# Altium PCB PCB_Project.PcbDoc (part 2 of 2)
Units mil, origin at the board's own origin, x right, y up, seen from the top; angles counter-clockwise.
Board outline 8500 x 3000 mil, 2 copper layers (Top Layer, Bottom Layer), stack 62 mil thick; 123 components, 59 nets, 356 pads, 0 vias.
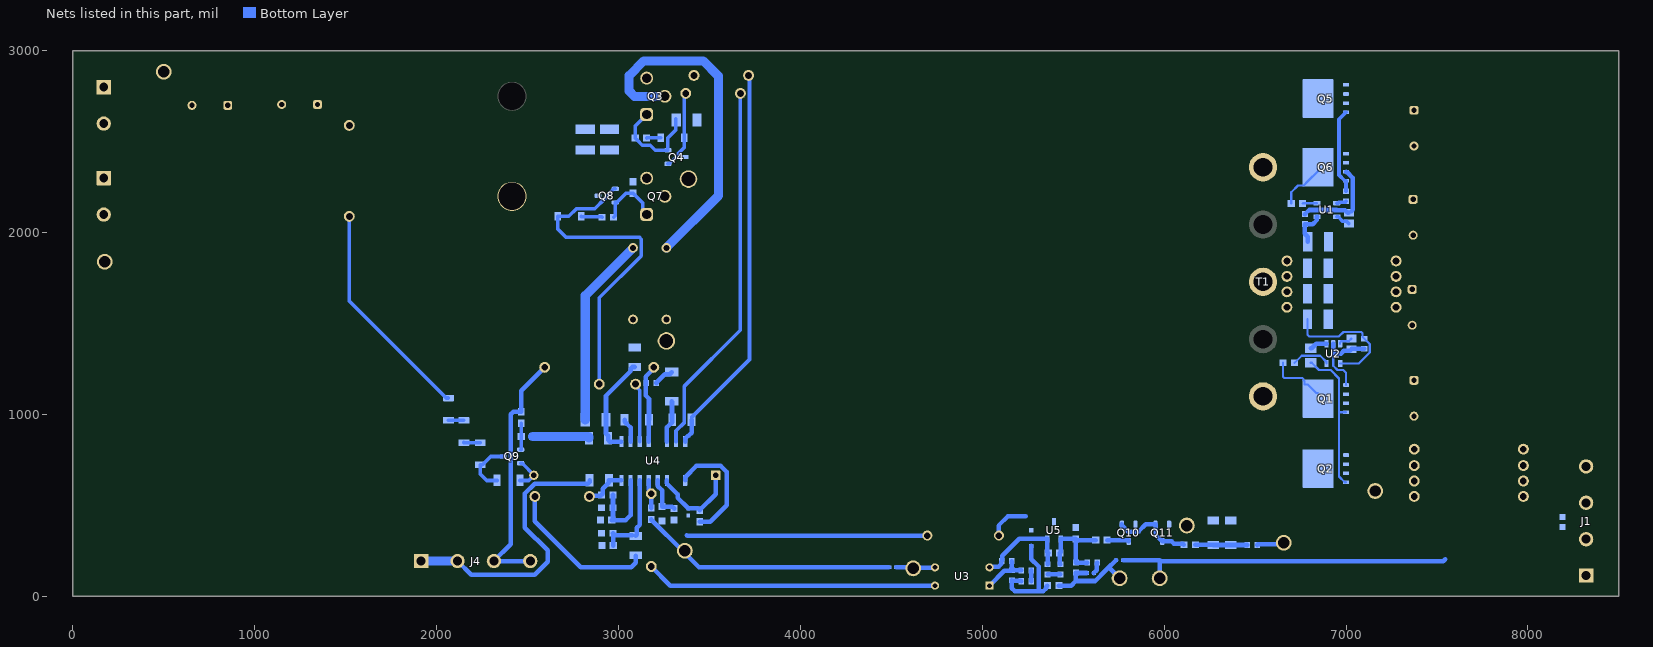
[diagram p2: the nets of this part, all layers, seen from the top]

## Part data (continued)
R16: library part CMP-0022684-3, "RES, 10.0 k, 1%, 0.1 W, 0603", Manufacturer=Panasonic, Power_W=100mW, Supplier Part Number 1=P10.0KHCT-ND, TempCo="100 ppm/C", Tolerance_%=1%, Value2=0.1W, Value_Code=10k0, ValueDisplayed=10.0k
R17 R19 R25: library part CMP-0087456-2, "3.3 MOhms ±1% 0.25W, 1/4W Chip Resistor 1206 (3216 Metric) Automotive AEC-Q200, High Voltage Thick Film", Manufacturer="Rohm Semiconductor", Power_W=250mW, TempCo=100ppm/°C, Tolerance_%=1%
R18: library part CMP-0026658-1, "RES, 10.0 k, 1%, 0.1 W, 0402", Manufacturer=Panasonic, Power_W=100mW, Supplier Part Number 1=P10.0KLCT-ND, TempCo="100 ppm/C", Tolerance_%=1%, Value2=0.1W, Value_Code=10k0, ValueDisplayed=10.0k
R20 R22: library part CMP-0023036-5, "RES, 33.2 k, 1%, 0.1 W, 0603", Manufacturer=Yageo, Power_W=100mW, Supplier Part Number 1=311-33.2KHRCT-ND, TempCo="100 ppm/C", Tolerance_%=1%, Value2=0.1W, Value_Code=33k2, ValueDisplayed=33.2k
R21: library part CMP-0022109-5, "RES, 1.00 k, 1%, 0.1 W, AEC-Q200 Grade 0, 0603", Manufacturer=Vishay-Dale, Power_W=100mW, Supplier Part Number 1=541-1.00KHCT-ND, TempCo="100 ppm/C", Tolerance_%=1%, Value2=0.1W, Value_Code=1k00, ValueDisplayed=1.00k
R23: library part CMP-0022735-5, "RES, 100 k, 1%, 0.1 W, 0603", Manufacturer=Yageo, Power_W=100mW, Supplier Part Number 1=311-100KHRCT-ND, TempCo="100 ppm/C", Tolerance_%=1%, Value2=0.1W, Value_Code=100k
R24: library part CMP-0016956-3, "RES, 3.01 M, 1%, 0.25 W, AEC-Q200 Grade 0, 1206", Manufacturer=Vishay-Dale, Power_W=250mW, Supplier Part Number 1=541-3.01MFCT-ND, TempCo="100 ppm/C", Tolerance_%=1%, Value2=0.25W, Value_Code=3M01, ValueDisplayed=3.01M
R26: library part CMP-0021990-4, "RES, 100 k, 1%, 0.1 W, AEC-Q200 Grade 0, 0603", Manufacturer=Vishay-Dale, Power_W=100mW, Supplier Part Number 1=541-100KHCT-ND, TempCo="100 ppm/C", Tolerance_%=1%, Value2=0.1W, Value_Code=100k
R27: library part CMP-0093609-1, "0Ω ±0 0.25W 1206 Thick Film Chip Resistor AEC-Q200 compliant", Manufacturer="Stackpole Electronics", Operating Temperature Range="-55°C to +155°C", Power_W=250mW
R28: library part CMP-0022763-5, "RES, 11.0 k, 1%, 0.1 W, 0603", Manufacturer=Yageo, Power_W=100mW, Supplier Part Number 1=311-11.0KHRCT-ND, TempCo="100 ppm/C", Tolerance_%=1%, Value2=0.1W, Value_Code=11k0, ValueDisplayed=11.0k
R30: library part CMP-0096703-1, "NTC Thermistor 470k 0603 (1608 Metric)", B Tolerance=3%, Digikey Part Number=495-B57371V2474J060CT-ND, Manufacturer=TDK, Mouser Part Number=871-B57371V2474J060, Operating Temperature Range="-55°C to +125°C", Power_W=180mW, Tolerance_%=5%
R31: library part CMP-0022828-5, "RES, 16.2 k, 1%, 0.1 W, 0603", Manufacturer=Yageo, Power_W=100mW, Supplier Part Number 1=311-16.2KHRCT-ND, TempCo="100 ppm/C", Tolerance_%=1%, Value2=0.1W, Value_Code=16k2, ValueDisplayed=16.2k
R32: library part CMP-0022941-4, "RES, 249 k, 1%, 0.1 W, 0603", Manufacturer=Yageo, Power_W=100mW, Supplier Part Number 1=311-249KHRCT-ND, TempCo="100 ppm/C", Tolerance_%=1%, Value2=0.1W, Value_Code=249k
R33: library part CMP-0023050-5, "RES, 35.7 k, 1%, 0.1 W, 0603", Manufacturer=Yageo, Power_W=100mW, Supplier Part Number 1=311-35.7KHRCT-ND, TempCo="100 ppm/C", Tolerance_%=1%, Value2=0.1W, Value_Code=35k7, ValueDisplayed=35.7k
R34: library part CMP-0023343-3, "RES, 0, 1%, 0.1 W, AEC-Q200 Grade 0, 0603", Manufacturer="Stackpole Electronics Inc", Power_W=100mW, Supplier Part Number 1=RMCF0603ZT0R00CT-ND, TempCo=ppm/C, Tolerance_%=1%, Value2=0.1W, Value_Code=0
T1: library part CMP-0120310-1, "Backlight LLC Transformer", Frequency_Fixed=80-250kHz, Manufacturer="Payton Planar", Operating Temperature Range=to, Voltage_Isolation_Vrms=2500VDC
TP5 Vin: library part CMP-0055147-2, "Test Point, Multipurpose, Red, TH", Color=Red, Manufacturer="Keystone Electronics", Supplier Part Number 1=36-5010-ND
TP6: library part CMP-0055150-2, "Test Point, Multipurpose, Orange, TH", Color=Orange, Manufacturer="Keystone Electronics", Supplier Part Number 1=36-5013-ND
TP7 TP8: library part CMP-0055149-2, "Test Point, Multipurpose, White, TH", Color=White, Manufacturer="Keystone Electronics", Supplier Part Number 1=36-5012-ND
U1 U2: library part CMP-0013047-3, "High-Frequency Multi-Mode Synchronous Rectifier Controller, DBV0005A (SOT-23-5)", Alternate Manufacturer="Texas Instruments", Alternate PartNumber=UCC24612-2DBVR
U3: library part CMP-0083653-1, "Optocoupler, 5.3 kV, 100-200% CTR, SMT", Manufacturer=Vishay-Semiconductor, Supplier Part Number 1=VO618A-3-ND, Voltage_Isolation_Vrms=5.3kV
U4: library part CMP-0095299-1, "750kHz Wide VIN/VOUT Range LLC Controller Optimized for Light Load Efficiency", Manufacturer="Texas Instruments", Max Supply Voltage=18.5V, Operating Temperature Range="-40°C to +150°C", Switching Frequency=30-750kHz
U5: library part CMP-0033066-1, "Low-Voltage Adjustable Precision Shunt Regulator, 129 ppm / degC, 80 mA, 0 to 70 degC, 3-pin SOT-23 (DBZ), Green (RoHS & no Sb/Br)", Manufacturer="Texas Instruments", Rating=Catalog, Temp Coeff(Max)(ppm/ degree C)=129

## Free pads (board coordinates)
  round 160 hole 150: 2(2414.9,2200) 2(2414.9,2750)

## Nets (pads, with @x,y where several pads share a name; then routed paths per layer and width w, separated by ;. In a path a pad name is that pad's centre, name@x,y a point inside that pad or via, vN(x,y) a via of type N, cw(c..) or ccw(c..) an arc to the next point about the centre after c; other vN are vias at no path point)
5VP_BL: C20.1 J14.2 R26.2 U4.8 | length 236.9
  Bottom Layer w25: J14.2@2840,550 2844.21,554.21 2902.49,554.21 R26.2@2906.7,558.42 2907.68,558.42 2913.88,564.62 2913.88,592.7 2947.09,625.91 C20.1@2947.09,638.7 U4.8@3016.26,638.7
BLK_BL: C32.1 J15.1 R33.2 U4.3 | length 498.9
  Bottom Layer w25: U4.3@3266.26,638.7 3266.26,621.38 3324.75,562.88 3324.75,542.49 C32.1@3382.56,484.68 3436.51,484.68 3439.8,481.39 3440.79,481.39 R33.2@3446.99,475.19 ; R33.2@3446.99,474.21 R33.2@3446.99,475.19 ; J15.1@3534.61,666.26 3534.61,562.81 R33.2@3446.99,475.19
EVDD: C2.2 C3.2 C8.2 C9.2 C12.1 J1.1 J1.2 J5.2 J6.2 J7.2 J8.2 R10.2 TP5.1 | length 1868.8
  Bottom Layer w25: R10.2@5774.69,200 5975,200 ; TP5.1@5975,100 5975,193.87 7533.87,193.87 7545,205
FB_BL: C24.1 J13.1 U4.5 | length 157.9
  Bottom Layer w25: U4.5@3166.26,638.7 3166.95,638.01 3166.95,587.52 3180,574.47 J13.1@3180,565 C24.1@3180,486.5
HO_BL: J18.1 U4.15 | length 2061.5
  Bottom Layer w20: U4.15@3316.26,851.3 3316.26,910.8 3362.36,956.9 3362.36,1156.88 3670,1464.51 J18.1@3670,2766.25
HS_BL: C26.2 J17.1 U4.16 | length 2133
  Bottom Layer w20: C26.2@3401.89,971.51 3401.89,984.31 3720,1302.42 3720,2835
  Bottom Layer w25: U4.16@3366.26,851.3 3366.26,868.62 3382.56,884.92 3387.25,884.92 3401.89,899.56 C26.2@3401.89,971.51
HVBUS: C1.1 C6.2 C7.2 C36.1 C37.1 J2.1 J2.2 J19.2 Q3.2 Vin.1 | length 1910.3
  Bottom Layer w50: Q3.2@3249.43,2750 3087.63,2750 3058.34,2779.29 3058.34,2863.34 3140,2945 3465.71,2945 3550,2860.71 3550,2203.54 C1.1@3263.31,1916.85
ISNS_BL: C13.2 C16.1 R5.2 U4.9 | length 555.8
  Bottom Layer w25: U4.9@3016.26,851.3 2952.3,851.3 2943.15,860.45 C16.1@2943.15,870.49 2943.15,883.28 2931.34,895.1 R5.2@2931.34,971.51 2931.34,1104.59 3066.65,1239.9 3066.65,1252.7 3075.81,1261.85 C13.2@3088.6,1261.85
LLC_VCC_BL: J4.3 J4.4 J20.2 R29.2 | length 1405.8
  Bottom Layer w25: J4.4@2515,195 J4.3@2315,195 2407.82,287.82 2407.82,1001.16 2422.46,1015.8 R29.2@2465.51,1015.8 2465.51,1131.39 J20.2@2594.12,1260
LO_BL: J16.1 U4.11 | length 325.2
  Bottom Layer w20: J16.1@3094.12,1167.36 3094.12,1156.54 3116.26,1134.4 U4.11@3116.26,851.3
NetC1_2: C1.2 C13.1 C14.1 Cr.1
NetC12_2: C12.2 J1.3 J1.4 J9.2 J10.2 J11.2 J12.2
NetC18_1: C18.1 U1.3 | length 81.2
  Bottom Layer w20: U1.3@6949.13,2087.6 6957.01,2087.6 6982.48,2062.13 7003.35,2062.13 C18.1@7015,2050.47
NetC19_1: C19.1 D4.1 R11.2 R34.1 | length 583.3
  Bottom Layer w25: C19.1@5214.88,83.66 5211.91,86.63 5165.41,86.63 R11.2@5162.44,89.6 5162.44,45.53 5177.97,30 5310,30 ; D4.1@5270,277.73 5270,204.95 5310,164.95 5310,30 ; R34.1@5358.26,60 5357.28,60 5351.08,53.8 5351.08,44.64 5336.43,30 5310,30
NetC19_2: C19.2 R8.2 | length 60
  Bottom Layer w25: C19.2@5270,83.66 R8.2@5270,143.66
NetC22_1: C22.1 U2.3 | length 79.7
  Bottom Layer w12: U2.3@6967.4,1389.13 6967.4,1397.01 6973.4,1403.01 7014.56,1403.01 C22.1@7030.22,1418.66
NetC23_1: C23.1 R10.1 R14.2 R34.2 TP6.1 | length 563.1
  Bottom Layer w25: R34.2@5421.26,60 5489.14,60 5514.25,85.11 ; R14.2@5514.25,131.47 5514.25,85.11 ; R14.2@5517.68,129.03 C23.1@5574.56,129.03 ; R10.1@5735.31,200 5689.8,154.48 ; TP6.1@5755,100 5700.52,154.48 5689.8,154.48 ; 5514.25,85.11 5620.48,85.11 5679.86,144.49 5679.86,144.54 5689.8,154.48
NetC23_2: C23.2 R16.2 | length 65
  Bottom Layer w25: C23.2@5613.94,129.03 5628.56,143.66 5628.56,183.34 R16.2@5631.81,186.59
NetC25_1: C25.1 R14.1 R16.1 R20.1 R22.2 R28.2 U5.1 | length 531.3
  Bottom Layer w25: R20.1@5429.25,176.59 5428.99,176.59 5425.75,179.84 C25.1@5425.75,239.03 5430.96,244.25 5430.96,316.1 U5.1@5431.65,316.79 R28.2@5514.25,316.79 R28.2@5514.25,316.2 ; R16.1@5576.69,186.59 R14.1@5514.25,186.59 R28.2@5514.25,316.2 ; R22.2@5623.5,310 5520.45,310 R28.2@5514.25,316.2
NetC25_2: C25.2 C27.2 R13.1 U3.2 U5.2 | length 548.8
  Bottom Layer w25: U3.2@5040,160 5043.88,163.88 5089.55,163.88 5104.19,178.52 5104.19,191.75 5110.69,198.25 5110.69,224.11 5203.37,316.79 U5.2@5356.85,316.79 5357.54,316.1 5357.54,244.25 C25.2@5362.75,239.03 5361,237.28 5361,178.34 C27.2@5359.25,176.59
NetC26_1: C26.1 D3.1 U4.14 | length 235.2
  Bottom Layer w25: U4.14@3266.26,851.3 3266.26,929.39 3295.59,958.72 C26.1@3295.59,971.51 3294.21,972.89 3294.21,1071.81 D3.1@3292.83,1073.18
NetC27_1: C27.1 R20.2 | length 70
  Bottom Layer w25: C27.1@5359.25,121.47 R20.2@5429.25,121.47
NetC28_1: C28.1 C29.1 R21.1 R23.2 | length 286.7
  Bottom Layer w25: R23.2@6171.5,285 6172.46,284.04 6269.04,284.04 C29.1@6270,283.07 C28.1@6365,283.07 R21.1@6457.44,283.07
NetC30_1: C30.1 R30.2 U4.4 | length 225.1
  Bottom Layer w25: U4.4@3216.26,638.7 3216.26,606.44 3239.68,583.01 R30.2@3239.68,494.15 3295.66,494.15 3305.5,484.31 C30.1@3305.5,483.32
NetC31_1: C31.1 R24.1 R32.2 U4.6 | length 491.7
  Bottom Layer w25: R32.2@2969.69,347.43 2970.67,347.43 2981.02,337.09 3065,337.09 R24.1@3075.83,337.09 ; R32.2@2970.59,346.53 2970.59,337.09 2970.59,280.9 C31.1@2971.5,280 ; R24.1@3095,333.15 3100.72,338.87 3100.72,377.66 3116.26,393.19 U4.6@3116.26,638.7
NetC33_1: C33.1 Q9.1 R29.1 | length 147.6
  Bottom Layer w20: Q9.1@2462.24,807.4 2463.7,807.4 2465.51,809.21 C33.1@2465.51,879.8 R29.1@2465.51,952.81
NetC34_1: C34.1 R26.1 R31.2 U4.7 | length 446.6
  Bottom Layer w25: C34.1@2963.31,420.33 C34.1@2963.49,420.33 ; R26.1@2969.69,558.42 R31.2@2969.69,488.26 2969.69,426.53 C34.1@2963.49,420.33 ; U4.7@3066.26,638.7 3066.26,446.57 3040.02,420.33 C34.1@2963.49,420.33
NetC35_1: C35.1 J20.1 R15.1 U4.12 | length 435.3
  Bottom Layer w25: U4.12@3166.26,851.3 3166.95,851.99 3166.95,970.78 C35.1@3167.68,971.51 3167.68,1086.93 3149.48,1105.13 3149.48,1174.25 3149.48,1209.18 3194.12,1253.82 J20.1@3194.12,1260
NetD1_1: D1.1 R1.1 | length 79.1
  Bottom Layer w20: R1.1@3154.76,2520.74 3155.78,2521.76 3232.01,2521.76 D1.1@3233.03,2522.77
NetD1_2: D1.2 J18.2 Q4.1 | length 401.5
  Bottom Layer w20: Q4.1@3271.78,2378.71 3279.65,2378.71 3328.71,2427.76 3328.71,2435.64 3361.97,2468.89 D1.2@3361.97,2522.77 J18.2@3361.97,2738.28
NetD2_1: D2.1 R3.1 | length 117.6
  Bottom Layer w20: D2.1@2794.47,2090 2796.97,2087.5 2907.5,2087.5 R3.1@2910,2085
NetD2_2: D2.2 J16.2 Q8.1 | length 1826.2
  Bottom Layer w20: J16.2@2894.12,1167.36 2894.12,1642.15 3124.45,1872.48 3124.45,1964.19 3112.73,1975.91 2709.63,1975.91 2665.53,2020 D2.2@2665.53,2090 2727.16,2090 2769.05,2131.89 2869.4,2131.89 2925.51,2188 2925.51,2192.1 2974.56,2241.16 Q8.1@2982.44,2241.16
NetD3_2: D3.2 R15.2 | length 112.5
  Bottom Layer w25: R15.2@3208.94,1172.88 R15.2@3207.56,1174.25 3207.56,1175.24 3254.23,1221.91 3280.93,1221.91 D3.2@3292.83,1233.82
NetHS_1: HS.1 J17.2 Q3.3 Q4.3 Q7.2 R2.1
NetJ13_2: J13.2 U3.4 | length 1603.5
  Bottom Layer w25: J13.2@3180,165 3285,60 U3.4@4740,60
NetJ14_1: J14.1 R24.2 | length 844.5
  Bottom Layer w25: J14.1@2540,550 2540,413.41 2793.41,160 3069.49,160 3095,185.51 R24.2@3095,222.91
NetJ15_2: J15.2 Q9.2 R27.1 | length 189.2
  Bottom Layer w20: R27.1@2457.99,638.01 2506.36,638.01 J15.2@2534.61,666.26 2534.61,668.11 2470.12,732.6 Q9.2@2462.24,732.6
NetJ19_1: J19.1 R17.2 | length 1231.6
  Bottom Layer w20: J19.1@1520,2090 1520,1624.21 2053.19,1091.02 R17.2@2065,1091.02
NetQ3_1: Q3.1 Q4.2 R1.2 R2.2 | length 538.7
  Bottom Layer w20: R1.2@3091.77,2520.74 3091.77,2586.77 Q3.1@3155,2650 ; R1.2@3101.45,2510.38 3131.34,2480.49 3174.47,2480.49 3201.45,2453.51 Q4.2@3271.78,2453.51 3271.78,2521.47 3315,2564.69 R2.2@3315,2624.93
NetQ7_1: Q7.1 Q8.2 R3.2 R4.2 | length 352.8
  Bottom Layer w20: R3.2@2972.99,2085 2973.74,2085 2982.44,2093.7 Q8.2@2982.44,2166.35 2990.31,2166.35 3041.33,2217.37 R4.2@3080,2217.37 3080,2216.39 3134.33,2162.05 3134.33,2120.67 Q7.1@3155,2100
NetQ9_3: Q9.3 R25.1 R27.2 | length 304.3
  Bottom Layer w20: R27.2@2332.01,638.01 2275,638.01 2240,673.01 R25.1@2240,723.98 2251.81,723.98 2297.83,770 Q9.3@2367.76,770
NetQ10_1: Q10.1 Q11.1 Q11.3 R23.1 | length 461.6
  Bottom Layer w25: Q10.1@5767.6,397.24 5767.6,390.75 5801.16,357.18 5859.19,357.18 5899.25,397.24 Q11.1@5952.6,397.24 5952.6,340.16 5982.81,309.94 5989.31,309.94 5990,309.25 Q11.3@5990,302.76 6040.69,302.76 6052.24,291.2 6102.3,291.2 R23.1@6108.5,285
NetQ10_3: Q10.3 R22.1 | length 125.3
  Bottom Layer w25: R22.1@5686.5,310 5804.25,310 5805,309.25 Q10.3@5805,302.76
NetR6_1: R6.1 U1.5 | length 80.4
  Bottom Layer w12: R6.1@6761.5,2160 6763.9,2162.4 U1.5@6840.87,2162.4
NetR7_2: R7.2 U1.1 | length 55
  Bottom Layer w20: U1.1@6949.13,2162.4 6957.01,2162.4 6961.3,2166.69 6994.21,2166.69 R7.2@6999.96,2172.44
NetR8_1: R8.1 R11.1 R13.2 U3.1 | length 260.7
  Bottom Layer w25: U3.1@5040,60 5121.47,141.47 5159.19,141.47 R11.1@5162.44,144.72 ; R13.2@5162.56,195 5162.5,194.94 5162.5,144.78 R11.1@5162.44,144.72 ; R8.1@5214.88,143.66 5214.35,144.19 5162.97,144.19 R11.1@5162.44,144.72
NetR9_1: R9.1 U2.5 | length 214.6
  Bottom Layer w12: R9.1@6716.5,1285 6717.48,1285 6756.35,1323.87 6857.46,1323.87 6892.6,1288.74 U2.5@6892.6,1280.87
NetR12_1: R12.1 U2.1 | length 97.6
  Bottom Layer w25: R12.1@6805,1365 6811.5,1365 6835.63,1389.13 U2.1@6892.6,1389.13
NetR17_1: R17.1 R19.2 | length 85.3
  Bottom Layer w20: R17.1@2065,968.98 2065.34,968.64 2149.66,968.64 R19.2@2150,968.3
NetR18_2: R18.2 TP7.1 U3.3 | length 217.3
  Bottom Layer w25: R18.2@4527.26,160 4614.48,160 TP7.1@4620,154.48 4622.76,157.24 4737.24,157.24 U3.3@4740,160
NetR19_1: R19.1 R25.2 | length 90.1
  Bottom Layer w20: R19.1@2150,846.26 2150.12,846.14 2239.88,846.14 R25.2@2240,846.02
NetR21_2: R21.2 TP8.1 | length 150.5
  Bottom Layer w25: R21.2@6512.56,283.07 6512.56,284.06 6515.81,287.3 6649.8,287.3 TP8.1@6657.5,295
PGND: C6.1 C7.1 C14.2 C15.2 C16.2 C20.2 C24.2 C30.2 C31.2 C32.2 C33.2 C34.2 C35.2 C36.2 C37.2 J3.1 J3.2 J4.1 J4.2 pad.2@2414.9,2200 PGND.1 Q7.3 Q8.3 R4.1 R5.1 R18.1 R30.1 R31.1 R32.1 R33.1 TP4.1 U4.1 U4.10 | length 6470.3
  Bottom Layer w25: J4.2@2115,195 2190,120 2539.3,120 2610.08,190.78 2610.08,253.58 2485,378.66 2485,566.24 2539.06,620.3 2831.63,620.3 2840.79,629.45 C20.2@2840.79,638.7 ; C35.2@3033.82,971.51 3033.82,961.67 3066.26,929.23 U4.10@3066.26,851.3 ; C24.2@3180,423.5 3180,422.52 3358.03,244.49 3442.52,160 R18.1@4485.93,160 ; U4.1@3366.26,638.7 3366.26,656.02 3427.84,717.6 3562.06,717.6 3594.87,684.79 3594.87,502.25 3503.84,411.22 R33.1@3446.99,411.22 ; 3375,337.09 3377.09,335 C15.2@4698.15,335
  Bottom Layer w50: J4.1@1915,195 J4.2@2115,195 ; C33.2@2528.5,879.8 2833.5,879.8 2836.85,876.46 C16.2@2836.85,870.49 ; R5.1@2817.17,971.51 2817.17,1654.02 C14.2@3080,1916.85
SGND: C2.1 C3.1 C4.1 C5.1 C8.1 C9.1 C10.2 C11.2 C15.1 C17.2 C18.2 C21.2 C22.2 C28.2 C29.2 D4.2 J9.1 J10.1 J11.1 J12.1 Q1.1 Q1.2 Q1.3 Q2.1 Q2.2 Q2.3 Q5.1 Q5.2 Q5.3 Q6.1 Q6.2 Q6.3 Q10.2 Q11.2 R28.1 TP1.1 TP2.1 U1.2 U2.2 U5.3 | length 1176.6
  Bottom Layer w12: 6930,1335 6930,1268.33 6953.19,1245.14 6984.82,1245.14 6999.96,1230 Q1.1@6999.96,1162.64
  Bottom Layer w25: C15.1@5091.85,335 5089.55,337.3 5089.55,389.97 5139.58,440 5240,440 ; C17.2@6773.37,2102.56 6774.35,2102.56 6796.79,2125 U1.2@6949.13,2125 6949.82,2124.31 6994.31,2124.31 7009.09,2109.53 C18.2@7015,2109.53 ; U2.2@6930,1389.13 6930,1335 6972.4,1335 6987.85,1350.45 7021.06,1350.45 C22.2@7030.22,1359.61 7031.63,1361.02 7098.58,1361.02 C21.2@7100,1362.44 ; Q6.3@6999.96,2335 7002.42,2332.54 7005.91,2332.54 7037.26,2301.18 7037.26,2125.89 C18.2@7030.06,2118.68
V+: C4.2 C5.2 C10.1 C11.1 C17.1 C21.1 J5.1 J6.1 J7.1 J8.1 T1.9 U1.4 U2.4 | length 915
  Bottom Layer w12: C11.1@6787.91,1525 6787.91,1438.88 6796.79,1430 6961.3,1430 6985.71,1454.41 7083.01,1454.41 7090.04,1447.38 7090.04,1427.31 7099.79,1417.56 C21.1@7100,1417.56 7100.98,1417.56 7130.61,1387.94 7130.61,1340.95 7070.53,1280.87 U2.4@6967.4,1280.87
  Bottom Layer w25: C5.2@6789.28,1950 6789.28,1977.56 6773.37,1993.47 C17.1@6773.37,2047.44 6817.44,2047.44 6840,2070 6840,2086.91 6840.69,2087.6 U1.4@6840.87,2087.6
VD1: Q5.5 Q5.6 Q5.7 Q5.8 Q5.9@6846.42,2737.64 Q6.5 Q6.6 Q6.7 Q6.8 Q6.9@6846.42,2360 R6.2 T1.11 | length 279.4
  Bottom Layer w12: R6.2@6698.5,2160 6698.5,2222.22 6735.99,2259.7 6766.98,2259.7 6788.54,2281.26 6846.42,2339.13 Q6.9@6846.42,2360
VD2: Q1.5 Q1.6 Q1.7 Q1.8 Q1.9@6846.42,1087.64 Q2.5 Q2.6 Q2.7 Q2.8 Q2.9@6846.42,702.64 R9.2 T1.7 | length 320
  Bottom Layer w12: R9.2@6653.5,1285 6653.5,1208.33 6660.53,1201.3 6759.95,1201.3 6766.98,1194.27 6766.98,1187.94 6772.03,1182.89 6772.03,1166.68 6772.33,1166.38 6788.54,1166.38 6836.5,1118.42 Q1.9@6846.37,1118.42
VG1: Q5.4 Q6.4 R7.1 | length 475.2
  Bottom Layer w20: R7.1@6999.96,2227.56 Q6.4@6999.96,2285 6993.07,2285 6961.3,2316.77 6961.3,2623.98 6993.03,2655.71 6993.03,2662.6 6993.07,2662.64 Q5.4@6999.96,2662.64
VG2: Q1.4 Q2.4 R12.2 | length 822
  Bottom Layer w12: R12.2@6805,1285 6811.5,1285 6851.36,1245.14 6915.17,1245.14 6961.3,1199.01 6961.3,1012.64 ; Q2.4@6999.96,627.64 6993.07,627.64 6961.3,659.41 6961.3,1012.64 ; Q1.4@6999.96,1012.64 6961.3,1012.64
pads on no net: Q1.9@6819.45,1035.28 Q1.9@6819.45,1087.64 Q1.9@6819.45,1140 Q1.9@6859.41,1087.64 Q1.9@6864.72,1035.28 Q1.9@6864.72,1087.64 Q1.9@6864.72,1140 Q1.9@6910,1035.28 Q1.9@6910,1087.64 Q1.9@6910,1140 Q1.9@6921.61,994.23 Q1.9@6921.61,1181.04 Q2.9@6819.45,650.28 Q2.9@6819.45,702.64 Q2.9@6819.45,755 Q2.9@6859.41,702.64 Q2.9@6864.72,650.28 Q2.9@6864.72,702.64 Q2.9@6864.72,755 Q2.9@6910,650.28 Q2.9@6910,702.64 Q2.9@6910,755 Q2.9@6921.61,609.23 Q2.9@6921.61,796.04 Q5.9@6819.45,2685.28 Q5.9@6819.45,2737.64 Q5.9@6819.45,2790 Q5.9@6859.41,2737.64 Q5.9@6864.72,2685.28 Q5.9@6864.72,2737.64 Q5.9@6864.72,2790 Q5.9@6910,2685.28 Q5.9@6910,2737.64 Q5.9@6910,2790 Q5.9@6921.61,2644.23 Q5.9@6921.61,2831.04 Q6.9@6819.45,2307.64 Q6.9@6819.45,2360 Q6.9@6819.45,2412.36 Q6.9@6859.41,2360 Q6.9@6864.72,2307.64 Q6.9@6864.72,2360 Q6.9@6864.72,2412.36 Q6.9@6910,2307.64 Q6.9@6910,2360 Q6.9@6910,2412.36 Q6.9@6921.61,2266.59 Q6.9@6921.61,2453.41 T1.8 T1.10

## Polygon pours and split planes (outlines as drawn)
HVBUS on Bottom Layer "BOTTOM_LAYER_HVBUS_P018" (solid, remove dead copper, pour order 18): 10,2500 11.38,2498.62 360,2498.62 360,2623.52 511.48,2775 710,2775 710,2767.78 815,2662.78 817.22,2665 940,2665 1035,2760 1227.92,2760 1447.92,2540 3128.06,2540 3200,2700 3297.5,2705 3297.5,2785 3119.71,2785 2909.71,2995 2366.5,2995 0,2995
PGND on Bottom Layer "BOTTOM_LAYER_PGND_P019" (solid, remove dead copper, pour order 19): 2185,1940 2460,1665 2905.25,1665 3112.73,1872.48 3109.34,1875.88 3109.34,1964.19 2709.63,1964.19 2635,2038.82 2635,2309.81 2194.81,2309.81 2185,2300
NetHS_1 on Bottom Layer "BOTTOM_LAYER_NETHS_1_P017" (solid, remove dead copper, pour order 17): 3120,2910 3120,2807.3 3142.3,2785 3210,2785 3215,2790 3314.96,2790 3335,2769.96 3335,2585.47 3205.54,2456.01 3205.54,2224.46 3260,2170 3410,2170 3520,2280 3520,2835 3445,2910
PGND on Bottom Layer "BOTTOM_LAYER_PGND_P016" (solid, remove dead copper, pour order 16): 10,1770 460,1770 882.1,2192.1 3125.42,2192.1 3225.83,2292.52 3225.83,2454.17 3200,2480 1460,2480 1195,2745 1095,2745 975,2625 820,2625 695,2750 535,2750 425,2640 425,2485 360,2420 10,2420
PGND on Bottom Layer "BOTTOM_LAYER_PGND_P015" (solid, remove dead copper, pour order 15): 3475.53,459.03 3151.46,459.03 3151.46,383.09 3075.63,307.27 2890,307.27 2890,255.71 2885.75,251.46 2942.2,195 3375,195 3475,295
PGND on Bottom Layer "BOTTOM_LAYER_PGND_P014" (solid, remove dead copper, pour order 14): 2859.87,1030 2770,1030 2645,905 2645,355 2805,195 3130,195 3130,762.28 3088.6,803.68 3088.6,1010.88 2994.12,1010.88 2990,1015 2990,943.38 3039.9,893.48 3039.9,800 2895,800 2890,805 2890,999.87
SGND on Bottom Layer "BOTTOM_LAYER_SGND_P013" (solid, remove dead copper, pour order 13): 5181.91,500 5181.91,235 5205.44,235 7390,235 7450,295 7450,531.54 6986.36,531.54 6980,525.18 6903.86,449.04 6852.9,500
NetC12_2 on Bottom Layer "BOTTOM_LAYER_NETC12_2_P012" (solid, remove dead copper, pour order 12): 8500,420 8005,420 7910,515 7910,895 8500,895
EVDD on Bottom Layer "BOTTOM_LAYER_EVDD_P011" (solid, remove dead copper, pour order 11): 7470.39,171.46 7641.85,0 8500,0 8500,382.44 8477.44,405 7995,405 7910,490 7910,919.35 7483.56,919.35 7470.39,932.52
EVDD on Bottom Layer "BOTTOM_LAYER_EVDD_P010" (solid, remove dead copper, pour order 10): 7234.99,2986.94 7234.99,1008.71 7373.7,870 7910,870 7910,2986.94
SGND on Bottom Layer "BOTTOM_LAYER_SGND_P009" (solid, remove dead copper, pour order 9): 6957.52,2992.88 6957.52,2275.41 7009.59,2275.41 7080,2205 7080,2032.4 7057.6,2010 6856.5,2010 6856.5,1453.55 6953.55,1453.55 6985,1485 7135,1485 7135,1220 6980,1220 6980,465 7385,465 7450,530 7450,985 7315,1120 7315,1201.3 7448.35,1334.65 7448.35,1491.65 7400.24,1539.76 7220,1539.76 7220,1863.47 7261.53,1905 7450,1905 7450,2030 7325,2155 7325,2310 7333.35,2310 7458.35,2435 7455,2438.35 7455,2527.64 7320,2662.64 7320,2992.88
V+ on Bottom Layer "BOTTOM_LAYER_V+_P008" (solid, remove dead copper, pour order 8): 6400,1815 6400,1665 6611.45,1453.55 6825,1453.55 6825,2012.99 6721.74,2012.99
VD2 on Bottom Layer "BOTTOM_LAYER_VD2_P007" (solid, remove dead copper, pour order 7): 6940,1218.92 6328.92,1218.92 6290,1180 6290,550 6375,465 6940,465
VD1 on Bottom Layer "BOTTOM_LAYER_VD1_P006" (solid, remove dead copper, pour order 6): 6621.58,2200 6940,2200 6940,2992.88 6415.24,2992.88 6225,2802.64 6225,2405 6430,2200
NetC1_2 on Bottom Layer "BOTTOM_LAYER_NETC1_2_P004" (solid, remove dead copper, pour order 4): 3000,1565 3000,1374.61 3034.61,1340 3355.45,1340 3355.45,1565

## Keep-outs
Keep-Out Layer:
  text ".Layer_Name" at 577,-858.49 h60

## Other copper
Top Layer:
  text ".Layer_Name" at 577,-858.49 h60
Bottom Layer:
  pour cut-out: 2483.74,2845 1865,2845 1555,2535 2735.71,2535
  text ".Layer_Name" at 577,-858.49 h60

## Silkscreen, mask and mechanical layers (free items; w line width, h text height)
Top Overlay:
  text "'.PRJ_Number'.PCB_Rev" at 650,55 h108.27
  text ".Layer_Name" at 577,-858.49 h60
Bottom Overlay:
  lines w10: 5205.44,411.02 5205.44,266.3 5205.44,250.57 5236,220 5320,220 5320,282.8 5325.5,288.3 5464.5,288.3 5464.5,25.5 5460.49,21.5 5320,21.5 5304,37.49 5304,219
  text ".Layer_Name" at 577,-858.49 h60
Top Paste:
  text ".Layer_Name" at 577,-858.49 h60
Bottom Paste:
  text ".Layer_Name" at 577,-858.49 h60
Top Solder:
  text ".Layer_Name" at 577,-858.49 h60
  text ".Layer_Name" at 577,-858.49 h60
Bottom Solder:
  text ".Layer_Name" at 577,-858.49 h60
Drill Guide:
  text ".Layer_Name" at 577,-858.49 h60
M1 Board Outline:
  the board outline again, w10
  text ".Layer_Name" at 577,-858.49 h60
M2 Board Dimensions:
  rectangle: 0,-275 125,-150
  rectangle: 125,-400 500,-275
  lines w7: 0,-275 1000,-275 ; 125,-400 125,-150 ; 250,-400 250,-150 ; 500,-400 500,-150 ; 750,-400 750,-150 ; 0,-400 1000,-400 1000,-150 0,-150 0,-400
  text ".Layer_Name" at 577,-858.49 h60
M3 3D STEP Top:
  text ".Layer_Name" at 577,-858.49 h60
M4 3D STEP Bottom:
  text ".Layer_Name" at 577,-858.49 h60
M5 Assembly Top:
  lines w10: -292,-930.17 6308,-930.17 ; -292,-726.83 6310,-726.83 ; -292,-523.5 -292,-1133.5 3713,-1133.5 6310,-1133.5 6310,-523.5 -291.5,-523.5 -291.5,-1133.5 1284,-1133.5 ; 2173,-1133.5 2173,-523.5 ; 3440,-726.83 3440,-523.5 ; 4280,-726.83 4280,-523.5 ; 4902,-1140 4902,-937.17
  text "COMPONENTS MARKED 'DNP' SHOULD NOT BE POPULATED." at 1153.5,-318.5 h60
  text "ASSEMBLY VARIANT:" at 1153,-434 h60
  text ".VariantName" at 2189,-434 h60
  text "PCB VIEWED FROM TOP SIDE" at -228.5,-655.67 h60
  text "BOARD #:" at 2248,-655.67 h60
  text ".PRJ_Number" at 2793.5,-655.67 h60
  text "REV:" at 3638,-655.67 h60
  text ".PCB_Rev" at 3929.5,-655.67 h60
  text "SVN REV:" at 4476,-655.67 h60
  text ".VersionControl_RevNumber" at 4982,-655.67 h60
  text "TID #:" at 2248,-859 h60
  text ".TID" at 2793.5,-859 h60
  text "PLOT NAME =" at -228.5,-1064.34 h60
  text ".plot_File_Name" at 577,-1064.34 h60
  text "GENERATED    :" at 2250,-1064.34 h60
  text ".Print_Date" at 3119.5,-1064.34 h60
  text ".Print_Time" at 3848.5,-1064.34 h60
  text "TEXAS INSTRUMENTS" at 5113,-1064.34 h60
M6 Assembly Bottom:
  lines w10: -292.5,-727.33 6309.5,-727.33 ; -290.5,-930.67 6309.5,-930.67 ; 1115.5,-1140.5 1115.5,-937.67 ; 1737.5,-727.33 1737.5,-524 ; 2577.5,-727.33 2577.5,-524 ; 3844.5,-1134 3844.5,-524 ; 4733.5,-1134 6309,-1134 6309,-524 -292.5,-524 -292.5,-1134 2304.5,-1134 6309.5,-1134 6309.5,-524
  text "COMPONENTS MARKED 'DNP' SHOULD NOT BE POPULATED." at 6102,-318 h60
  text ".VariantName" at 5058,-434 h60
  text "ASSEMBLY VARIANT:" at 6097,-434 h60
  text ".VersionControl_RevNumber" at 1035.5,-656.17 h60
  text "SVN REV:" at 1541.5,-656.17 h60
  text ".PCB_Rev" at 2088,-656.17 h60
  text "REV:" at 2379.5,-656.17 h60
  text ".PRJ_Number" at 3224,-656.17 h60
  text "BOARD #:" at 3769.5,-656.17 h60
  text "PCB VIEWED FROM BOTTOM SIDE" at 6246,-656.17 h60
  text ".TID" at 3224,-859.5 h60
  text "TID #:" at 3769.5,-859.5 h60
  text "TEXAS INSTRUMENTS" at 904.5,-1064.84 h60
  text ".Print_Time" at 2169,-1064.84 h60
  text ".Print_Date" at 2898,-1064.84 h60
  text "GENERATED    :" at 3767.5,-1064.84 h60
  text ".plot_File_Name" at 5440.5,-1064.84 h60
  text "PLOT NAME =" at 6246,-1064.84 h60
M9 Title Sheet:
  drawing of 57 lines, arcs and shapes, not listed
  text "1" at 739.84,8036.5 h70
  text "2" at 3235.5,8036.5 h70
  text "3" at 5724.84,8036.5 h70
  text "4" at 8231.51,8036.5 h70
  text "5" at 10730.5,8036.5 h70
  text "6" at 13235.5,8036.5 h70
  text "A" at -416.5,6893.5 h70
  text "A" at 14383.5,6893.5 h70
  text "B" at -416.5,4513.5 h70
  text "B" at 14383.5,4513.5 h70
  text "C" at -416.5,2138.5 h70
  text "C" at 14383.5,2138.5 h70
  text "PROJECT TITLE:" at 11343.5,277.5 h45
  text ".PRJ_Title" at 11393.5,144.17 h70
  text "DESIGNED FOR:" at 11343.5,-23.5 h45
  text ".PRJ_Customer" at 11393.5,-163.5 h70
  text "D" at -416.5,-231.5 h70
  text "D" at 14383.5,-231.5 h70
  text "FILE NAME:" at 11343.5,-323.5 h45
  text ".PCB_File_Name_No_Path" at 11393.5,-443.5 h70
  text "Texas Instruments (TI) and/or its licensors do not warrant the accuracy or completeness of this specification" at 6374,-605.34 h45
  text "ENGINEER:" at 11343.5,-613.5 h45
  text "LAYOUT BY:" at 12848.5,-613.5 h45
  text "or any information contained therein. TI and/or its licensors do not warrant that this design will meet" at 6329.01,-718 h45
  text ".PRJ_Engineer" at 11393.5,-768.49 h70
  text ".PCB_Layout" at 12899,-768.49 h70
  text "the specifications, will be suitable for your application or fit for any particular purpose, or will operate in" at 6329.01,-830.67 h45
  text ".Layer_Name" at 577,-858.49 h60
  text "ALTIUM DESIGNER VERSION:" at 12848.5,-923.5 h45
  text "an implementation. TI and/or its licensors do not warrant that the design is production worthy. You should" at 6329.01,-943.33 h45
  text "completely validate and test your design implementation to confirm the system functionality for your application." at 6374,-1056 h45
  text ".print_Scale" at 11393.5,-1056.83 h70
  text ".Application_BuildNumber" at 12899,-1056.83 h70
  text "1" at 739.84,-1263.5 h70
  text "2" at 3235.5,-1263.5 h70
  text "3" at 5724.84,-1263.5 h70
  text "4" at 8231.51,-1263.5 h70
  text "5" at 10730.5,-1263.5 h70
  text "6" at 13235.5,-1263.5 h70
M10 Fab Notes:
  drawing of 189 lines, arcs and shapes, not listed
  text "DESIGN INFORMATION" at 12382.02,6356.17 h60
  text "MIN. TRACK WIDTH:" at 11737.46,6224.05 h60
  text "8" at 12833.7,6224.05 h60
  text "MIL" at 12988.46,6224.05 h60
  text "7.874" at 12667.32,6102.36 h60
  text "MIN. CLEARANCE:" at 11737.46,6099.92 h60
  text "MIL" at 12988.46,6099.92 h60
  text "MIN. VIA PAD SIZE:" at 11737.46,5975.8 h60
  text "24" at 12803.71,5975.8 h60
  text "MIL" at 12988.46,5975.8 h60
  text "0.05mm (2MIL)" at 12432.46,5845.9 h60
  text "MINIMUM ANNULAR RING" at 11408.23,5837.67 h60
  text "EXTERNAL" at 13140.46,5837.67 h60
  text "PER" at 11608.23,5727.55 h60
  text "IPC-D-275 CLASS 2 LEVEL C" at 11828.23,5727.54 h60
  text "MIL, HOLES" at 13316.46,5627.07 h60
  text "+/-" at 12924,5618.48 h60
  text "+/-" at 13778,5618.48 h60
  text "REGISTRATION TOLERANCES:" at 11408.23,5617.42 h60
  text "METAL" at 12608,5617.42 h60
  text "5" at 13184.2,5617.42 h60
  text "3" at 14017.2,5617.42 h60
  text "MIL" at 14133.46,5617.42 h60
  text "HOLE SIZE TOLERANCE (UNLESS OTHERWISE SPECIFIED):" at 11408.23,5519.1 h60
  text "+/-" at 13778,5516.23 h60
  text "3" at 14017.2,5515.17 h60
  text "MIL" at 14133.46,5515.17 h60
  text "MATERIAL:" at 11333.46,5377.52 h60
  text "FR-4 High Tg" at 12319.9,5249 h60
  text "X" at 12175.46,5241.01 h60
  text "FR-4" at 11754.46,5236.49 h60
  text "OTHER" at 13242.46,5236.49 h60
  text "62 MIL (1.6mm) +/-10%" at 12074.56,5093.46 h60
  text "X" at 11954.46,5091.01 h60
  text "THICKNESS:" at 11408.23,5085.24 h60
  text "OTHER" at 13359.46,5085.24 h60
  text "TOLERANCE:" at 11408.23,4946.92 h60
  text "X" at 12256.46,4946.92 h60
  text "ANSI IPC-6012 TYPE 3 CLASS 2" at 12434.48,4946.92 h60
  text "OTHER +/-" at 12434.46,4802.73 h60
  text "BOW & TWIST:" at 11408.23,4657.54 h60
  text "X" at 12256.46,4657.54 h60
  text "ANSI IPC-6012 TYPE 3 CLASS 2" at 12434.48,4657.54 h60
  text "OTHER +/-" at 12434.46,4510.85 h60
  text "DRILLING:" at 11333.46,4380.23 h60
  text "NC_DRILL FILES" at 13094.46,4275.04 h60
  text "REFERENCE:" at 11408.23,4271.1 h60
  text "X" at 12065.46,4271.01 h60
  text "AS SHOWN" at 12243.46,4271.1 h60
  text "X" at 12966.46,4271.1 h60
  text "OTHER" at 13392.46,4128.85 h60
  text "PTH COPPER THICKNESS:" at 11407.91,4125.32 h60
  text "X" at 12547.14,4125.32 h60
  text "20-30 um" at 12675.14,4125.32 h60
  text "BOARD FINISH:" at 11333.46,3977.73 h60
  text "SILKSCREEN:" at 11488.68,3867.6 h60
  text "X" at 12446.46,3867.6 h60
  text "TOP" at 12563.46,3867.6 h60
  text "X" at 12956.46,3867.6 h60
  text "BOTTOM" at 13074.46,3867.6 h60
  text "SILKSCREEN COLOR:" at 11488.68,3712.41 h60
  text "X" at 12445.46,3712.41 h60
  text "WHITE" at 12563.46,3712.41 h60
  text "OTHER" at 13074.46,3712.41 h60
  text "X" at 12576.46,3568.96 h60
  text "GREEN" at 12694.46,3568.96 h60
  text "OTHER" at 13312.46,3568.96 h60
  text "SOLDER RESIST COLOR:" at 11488.68,3562.1 h60
  text "X" at 12576.46,3414.71 h60
  text "MATTE" at 12694.46,3414.71 h60
  text "SEMI-GLOSS" at 13312,3414.07 h60
  text "IMMERSION GOLD (ENIG)" at 12394.46,3241.94 h60
  text "ENEPIG" at 13732,3234.72 h60
  text "SURFACE FINISH:" at 11333.46,3233.72 h60
  text "X" at 12216.46,3233.72 h60
  text "IMM. TIN/SILVER OR EQUIV" at 11663,3096.4 h60
  text "OTHER" at 13094.46,3092.47 h60
  text "ARRAY/PANEL:" at 11333.46,2937.09 h60
  text "CUT AND TRIM PER M1 BOARD OUTLINE" at 12394.46,2928.87 h60
  text "N.C. ROUTE" at 12394.46,2792.9 h60
  text "X" at 13082.46,2792.9 h60
  text "V. SCORE" at 13260.46,2792.9 h60
  text "CERTIFICATION:" at 11333.46,2663.77 h60
  text "MATERIALS AND WORKMANSHIP FOR ALL PCBS" at 12058.46,2663.77 h60
  text "TO MEET OR EXCEED THE REQUIREMENTS OF:" at 12058.46,2569.71 h60
  text "X" at 11695.97,2441.08 h60
  text "ANSI IPC-A-600F CLASS ->" at 11823.96,2441.08 h60
  text "X" at 13471.97,2441.08 h60
  text "2" at 13581.96,2441.08 h60
  text "1" at 13266.96,2439.58 h60
  text "3" at 13935.96,2439.58 h60
  text "X" at 12507.97,2293.39 h60
  text "RoHS" at 12635.96,2293.39 h60
  text "OTHER" at 13280.36,2293.39 h60
  text "PER ORDER" at 13677.42,2293.39 h60
  text "ALL BOARDS MUST MEET OR EXCEED UL94-V0 REQUIREMENTS." at 11361,2139.57 h60
  text "PCB MUST BEAR THE UL94V-0 UL REGISTERED MATERIAL ID NUMBER" at 11361,2023.5 h60
  text "ADDITIONAL REQUIREMENTS:" at 11333.46,1854.08 h60
  text "MICROSECTION:" at 11408.23,1746.95 h60
  text "YES" at 12313.96,1746.95 h60
  text "REQUIRED" at 13175.46,1602.62 h60
  text "BARE BOARD ELEC. TEST:" at 11408.23,1599.76 h60
  text "NONE" at 12713.96,1599.76 h60
  text "X" at 13057.46,1599.76 h60
  text "PER ORDER" at 13767.46,1599.76 h60
  text "XX MIL VIAS REQUIRE NON-CONDUCTIVE FILL AND PLANARIZE" at 11576.38,1394.82 h59
  text "XX MIL VIAS REQUIRE CONDUCTIVE FILL AND PLANARIZE" at 11584.38,1290.84 h60
  text "OUTER XX MIL TRACES REQUIRE 50 OHM SINGLE-ENDED IMPEDANCE" at 11583.39,1127.46 h58
  text "LAYER 2 & 3 (INNER LAYERS) XX MIL WIDE, XX MIL SPACE / TRACES REQUIRE 100 OHM DIFFERENTIAL IMPEDANCE" at 11575.39,891.74 h60
  text ".Layer_Name" at 577,-858.49 h60
M11 Gerber Information:
  lines w10: -292,-930.17 6308,-930.17 ; -292,-726.83 6310,-726.83 ; -292,-523.5 -292,-1133.5 3713,-1133.5 6310,-1133.5 6310,-523.5 -291.5,-523.5 -291.5,-1133.5 1284,-1133.5 ; 2173,-1133.5 2173,-523.5 ; 3440,-726.83 3440,-523.5 ; 4280,-726.83 4280,-523.5 ; 4902,-1140 4902,-937.17
  text "ALL ARTWORK VIEWED FROM TOP SIDE" at -228.5,-655.67 h60
  text "BOARD #:" at 2248,-655.67 h60
  text ".PRJ_Number" at 2793.5,-655.67 h60
  text "REV:" at 3638,-655.67 h60
  text ".PCB_Rev" at 3929.5,-655.67 h60
  text "SVN REV:" at 4476,-655.67 h60
  text ".VersionControl_RevNumber" at 4982,-655.67 h60
  text "LAYER NAME =" at -228.5,-858.49 h60
  text "TID #:" at 2248,-859 h60
  text ".TID" at 2793.5,-859 h60
  text "PLOT NAME =" at -228.5,-1064.34 h60
  text ".plot_File_Name" at 577,-1064.34 h60
  text "GENERATED    :" at 2250,-1064.34 h60
  text ".Print_Date" at 3119.5,-1064.34 h60
  text ".Print_Time" at 3848.5,-1064.34 h60
  text "TEXAS INSTRUMENTS" at 5113,-1064.34 h60
M12 Stackup:
  drawing of 191 lines, arcs and shapes, not listed
  text "Layer" at 9775.34,7790 h60
  text "Name" at 10185.26,7790 h60
  text "Material" at 11115,7790 h60
  text "Thickness" at 11974.77,7790 h60
  text "Constant" at 12624.6,7790 h60
  text "Board Layer Stack" at 13194.46,7790 h60
  text "Top Overlay" at 10185.26,7670 h60
  text "Top Solder" at 10185.26,7550 h60
  text "Solder Resist" at 11115,7550 h60
  text "0.40mil" at 11974.77,7550 h60
  text "3.5" at 12624.6,7550 h60
  text "1" at 9775.34,7430 h60
  text "Top Layer" at 10185.26,7430 h60
  text "2.80mil" at 11974.77,7430 h60
  text "Dielectric1" at 10185.26,7310 h60
  text "FR-4 High Tg" at 11115,7310 h60
  text "56.40mil" at 11974.77,7310 h60
  text "4.8" at 12624.6,7310 h60
  text "2" at 9775.34,7190 h60
  text "Bottom Layer" at 10185.26,7190 h60
  text "2.80mil" at 11974.77,7190 h60
  text "Bottom Solder" at 10185.26,7070 h60
  text "Solder Resist" at 11115,7070 h60
  text "0.40mil" at 11974.77,7070 h60
  text "3.5" at 12624.6,7070 h60
  text "Bottom Overlay" at 10185.26,6950 h60
  text ".Layer_Name" at 577,-858.49 h60
M13 Component Bodies Top:
  text ".Layer_Name" at 577,-858.49 h60
M14 Component Bodies Bottom:
  text ".Layer_Name" at 577,-858.49 h60
M15 Courtyards Top:
  text ".Layer_Name" at 577,-858.49 h60
M16 Courtyards Bottom:
  text ".Layer_Name" at 577,-858.49 h60
Drill Drawing:
  circle w10: c5328.72,5078.44 r16.58
  circle w10: c5328.72,5078.44 r27.63
  circle w10: c5328.72,4083.88 r27.63
  lines w10: 5301.09,3862.87 5356.34,3862.87 5328.72,3807.62 5301.09,3862.87 ; 5301.09,4180.58 5356.34,4180.58 5356.34,4235.83 5301.09,4235.83 5301.09,4180.58 ; 5301.09,4318.71 5314.9,4318.71 5314.9,4304.9 5342.53,4304.9 5342.53,4318.71 5356.34,4318.71 5356.34,4346.34 5342.53,4346.34 5342.53,4360.15 5314.9,4360.15 5314.9,4346.34 5301.09,4346.34 5301.09,4318.71 ; 5301.09,4443.03 5314.9,4443.03 5314.9,4429.22 5342.53,4429.22 5342.53,4443.03 5356.34,4443.03 5356.34,4470.66 5342.53,4470.66 5342.53,4484.47 5314.9,4484.47 5314.9,4470.66 5301.09,4470.66 5301.09,4443.03 ; 5301.09,4553.54 5301.09,4567.35 5314.9,4581.16 5301.09,4594.98 5301.09,4608.79 5314.9,4608.79 5328.72,4594.98 5342.53,4608.79 5356.34,4608.79 5356.34,4594.98 5342.53,4581.16 5356.34,4567.35 5356.34,4553.54 5342.53,4553.54 5328.72,4567.35 5314.9,4553.54 5301.09,4553.54 ; 5301.09,4733.11 5356.34,4733.11 5328.72,4677.86 5301.09,4733.11 ; 5301.09,4829.8 5328.72,4802.18 5356.34,4829.8 5328.72,4857.43 5301.09,4829.8 ; 5301.09,4926.5 5328.72,4940.31 5356.34,4926.5 5342.53,4954.12 5356.34,4981.75 5328.72,4967.94 5301.09,4981.75 5314.9,4954.12 5301.09,4926.5 ; 5301.09,5188.95 5314.9,5188.95 5328.72,5175.14 5342.53,5188.95 5356.34,5188.95 5342.53,5202.76 5356.34,5216.58 5342.53,5216.58 5328.72,5230.39 5314.9,5216.58 5301.09,5216.58 5314.9,5202.76 5301.09,5188.95 ; 5301.09,5299.46 5356.34,5299.46 5356.34,5354.71 5301.09,5354.71 5301.09,5299.46 ; 5312.14,3851.82 5345.29,3851.82 5328.72,3818.67 5312.14,3851.82 ; 5312.14,4448.55 5320.43,4448.55 5320.43,4440.27 5337.01,4440.27 5337.01,4448.55 5345.29,4448.55 5345.29,4465.13 5337.01,4465.13 5337.01,4473.42 5320.43,4473.42 5320.43,4465.13 5312.14,4465.13 5312.14,4448.55 ; 5312.14,5310.51 5345.29,5310.51 5345.29,5343.66 5312.14,5343.66 5312.14,5310.51
  lines w12: 5251,3770.32 8375.89,3770.32 ; 5251,5386.48 8375.89,5386.48 ; 5588.86,3646 5588.86,5510.8 ; 5860.92,3646 5860.92,5510.8 ; 6450.83,3646 6450.83,5510.8 ; 6709.97,3646 6709.97,5510.8 ; 7085.13,3646 7085.13,5510.8 ; 7809.46,3646 7809.46,5510.8 ; 5251,3646 8375.89,3646 8375.89,5510.8 5251,5510.8 5251,3646
  text "Symbol" at 5325.59,5423.78 h72
  text "Count" at 5626.16,5423.78 h72
  text "Hole Size" at 5898.22,5423.78 h72
  text "Plated" at 6488.13,5423.78 h72
  text "Hole Type" at 6747.27,5423.78 h72
  text "Drill Layer Pair" at 7122.43,5423.78 h72
  text "Hole Tolerance" at 7846.76,5423.78 h72
  text "4" at 5626.16,5299.46 h60
  text "25.59mil (0.650mm)" at 5898.22,5299.46 h60
  text "PTH" at 6488.13,5299.46 h60
  text "Round" at 6747.27,5299.46 h60
  text "Top Layer - Bottom Layer" at 7122.43,5299.46 h60
  text "12" at 5626.16,5175.14 h60
  text "29.53mil (0.750mm)" at 5898.22,5175.14 h60
  text "PTH" at 6488.13,5175.14 h60
  text "Round" at 6747.27,5175.14 h60
  text "Top Layer - Bottom Layer" at 7122.43,5175.14 h60
  text "2" at 5626.16,5050.82 h60
  text "31.50mil (0.800mm)" at 5898.22,5050.82 h60
  text "PTH" at 6488.13,5050.82 h60
  text "Round" at 6747.27,5050.82 h60
  text "Top Layer - Bottom Layer" at 7122.43,5050.82 h60
  text "4" at 5626.16,4926.5 h60
  text "33.47mil (0.850mm)" at 5898.22,4926.5 h60
  text "PTH" at 6488.13,4926.5 h60
  text "Round" at 6747.27,4926.5 h60
  text "Top Layer - Bottom Layer" at 7122.43,4926.5 h60
  text "2" at 5626.16,4802.18 h60
  text "35.43mil (0.900mm)" at 5898.22,4802.18 h60
  text "PTH" at 6488.13,4802.18 h60
  text "Round" at 6747.27,4802.18 h60
  text "Top Layer - Bottom Layer" at 7122.43,4802.18 h60
  text "18" at 5626.16,4677.86 h60
  text "37.00mil (0.940mm)" at 5898.22,4677.86 h60
  text "PTH" at 6488.13,4677.86 h60
  text "Round" at 6747.27,4677.86 h60
  text "Top Layer - Bottom Layer" at 7122.43,4677.86 h60
  text "12" at 5626.16,4553.54 h60
  text "38.00mil (0.965mm)" at 5898.22,4553.54 h60
  text "PTH" at 6488.13,4553.54 h60
  text "Round" at 6747.27,4553.54 h60
  text "Top Layer - Bottom Layer" at 7122.43,4553.54 h60
  text "12" at 5626.16,4429.22 h60
  text "49.21mil (1.250mm)" at 5898.22,4429.22 h60
  text "PTH" at 6488.13,4429.22 h60
  text "Round" at 6747.27,4429.22 h60
  text "Top Layer - Bottom Layer" at 7122.43,4429.22 h60
  text "6" at 5626.16,4304.9 h60
  text "51.18mil (1.300mm)" at 5898.22,4304.9 h60
  text "PTH" at 6488.13,4304.9 h60
  text "Round" at 6747.27,4304.9 h60
  text "Top Layer - Bottom Layer" at 7122.43,4304.9 h60
  text "9" at 5626.16,4180.58 h60
  text "63.00mil (1.600mm)" at 5898.22,4180.58 h60
  text "PTH" at 6488.13,4180.58 h60
  text "Round" at 6747.27,4180.58 h60
  text "Top Layer - Bottom Layer" at 7122.43,4180.58 h60
  text "2" at 5626.16,4056.26 h60
  text "75.00mil (1.905mm)" at 5898.22,4056.26 h60
  text "PTH" at 6488.13,4056.26 h60
  text "Round" at 6747.27,4056.26 h60
  text "Top Layer - Bottom Layer" at 7122.43,4056.26 h60
  text "5" at 5626.16,3931.94 h60
  text "102.36mil (2.600mm)" at 5898.22,3931.94 h60
  text "PTH" at 6488.13,3931.94 h60
  text "Round" at 6747.27,3931.94 h60
  text "Top Layer - Bottom Layer" at 7122.43,3931.94 h60
  text "D" at 5300.31,3921.94 h55.25
  text "2" at 5626.16,3807.62 h60
  text "150.00mil (3.810mm)" at 5898.22,3807.62 h60
  text "PTH" at 6488.13,3807.62 h60
  text "Round" at 6747.27,3807.62 h60
  text "Top Layer - Bottom Layer" at 7122.43,3807.62 h60
  text "90 Total" at 5626.16,3683.3 h60
  text ".Layer_Name" at 577,-858.49 h60
M17 Embedded Cavity:
  text ".Layer_Name" at 577,-858.49 h60
M18 Embedded Assembly:
  text ".Layer_Name" at 577,-858.49 h60
M19 Embedded Keepout:
  text ".Layer_Name" at 577,-858.49 h60

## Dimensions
0,-400 to 1000,-400 on M2 Board Dimensions
0,0 to 8500,0 on M2 Board Dimensions
0,0 to 0,3000 on M2 Board Dimensions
